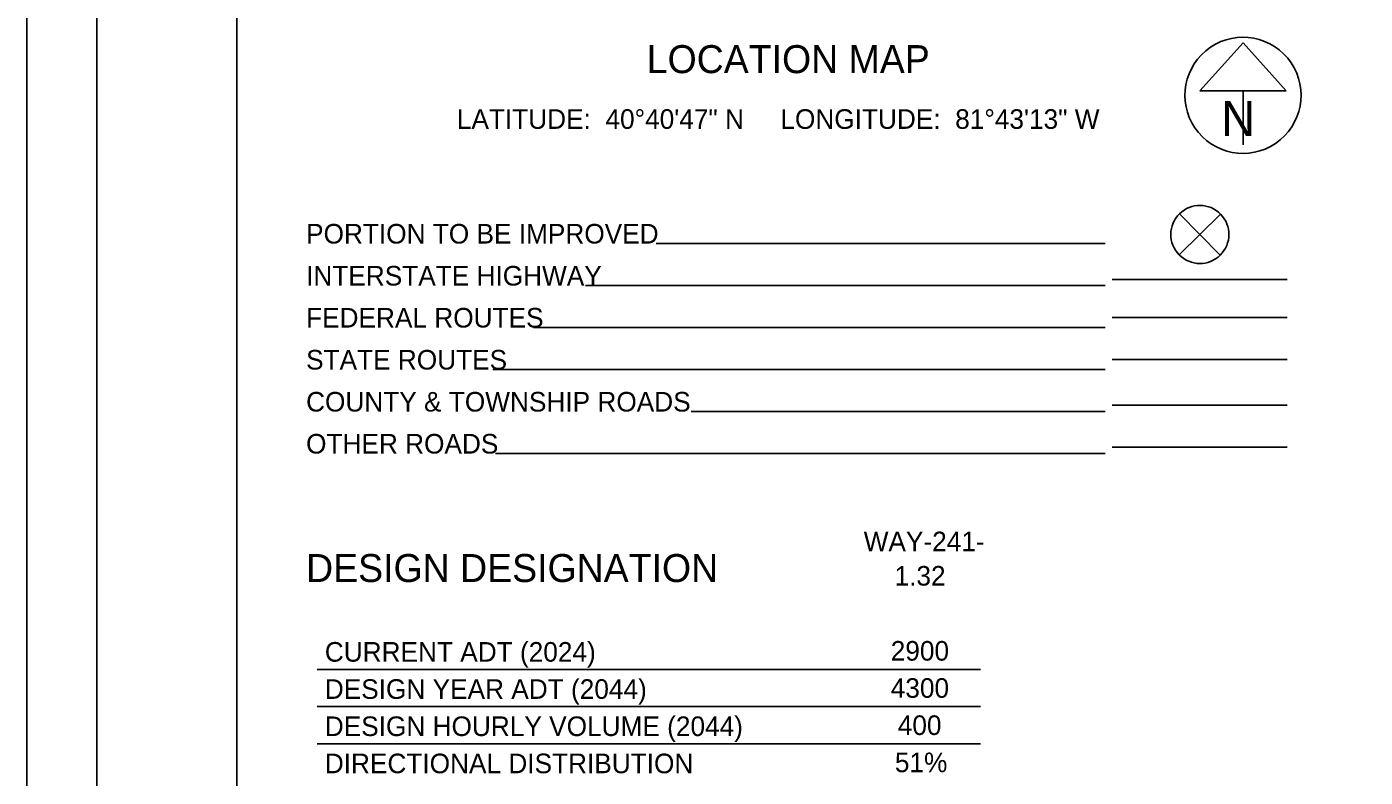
# Model space of a CAD drawing. Extents: x -21.1 to 50.3, y -4.9 to 22.1.
# Drawn here: x 0 to 9.56, y 8.56 to 13.93 of the extents above; entities that cross this region are included whole.
import ezdxf

# ---------------------------------------------------------------- set-up
doc = ezdxf.new("R2010")
doc.units = 0
for name, color, linetype in [('Default', 7, 'Continuous'), ('SH_Border', 7, 'Continuous'), ('SH_Cut_Line', 7, 'Continuous'), ('SH_Data', 7, 'Continuous'), ('SH_Text', 7, 'Continuous')]:
    doc.layers.add(name, color=color, linetype=linetype)

msp = doc.modelspace()

# ---------------------------------------------------------------- linework, layer by layer
at = {"layer": 'Default'}
for p, q in [((2.0726, 9.3348), (6.8094, 9.3348)), ((2.0726, 9.0692), (6.8094, 9.0692)), ((2.0726, 8.8036), (6.8094, 8.8036))]:
    msp.add_line(p, q, dxfattribs=at)
at = {"layer": 'SH_Border'}
for points in [[(0.5, 21.5), (1.5, 21.5), (1.5, 0.5), (0.5, 0.5)], [(1.5, 21.5), (33.5, 21.5), (33.5, 0.5), (1.5, 0.5)]]:
    msp.add_lwpolyline(points, close=True, dxfattribs=at)
at = {"layer": 'SH_Cut_Line'}
msp.add_lwpolyline([(0, 0), (34, 0), (34, 22), (0, 22)], close=True, dxfattribs=at)
at = {"layer": 'SH_Data'}
for p, q in [((8.6845, 13.8091), (8.3769, 13.4678)), ((8.9921, 13.4678), (8.6845, 13.8091)), ((8.3769, 13.4678), (8.9921, 13.4678)), ((8.6845, 13.4678), (8.6845, 13.0811)), ((8.6845, 13.4353), (8.6845, 13.4353)), ((8.6845, 13.4353), (8.6845, 13.4353)), ((8.5245, 12.5868), (8.2285, 12.2962)), ((8.2312, 12.5895), (8.5218, 12.2935)), ((7.7, 12.3767), (4.4937, 12.3767)), ((7.7, 12.0767), (3.9895, 12.0767)), ((9, 12.1207), (7.75, 12.1207)), ((7.7, 11.7767), (3.6192, 11.7767)), ((9, 11.8491), (7.75, 11.8491)), ((7.7, 11.4767), (3.3288, 11.4767)), ((9, 11.5491), (7.75, 11.5491)), ((9, 11.2223), (7.75, 11.2223)), ((7.7, 11.1767), (4.7452, 11.1767)), ((9, 10.9223), (7.75, 10.9223)), ((7.7, 10.8767), (3.3471, 10.8767))]:
    msp.add_line(p, q, dxfattribs=at)
for centre, radius, start, end in [((8.6845, 13.4353), 0.4148, 129.77984, 129.76332), ((8.3765, 12.4415), 0.2074, 134.48425, 134.46773)]:
    msp.add_arc(centre, radius, start, end, dxfattribs=at)

# ---------------------------------------------------------------- texts
at = {"layer": 'Default'}
for s, p in [('WAY-241-', (5.976, 10.1786)), ('1.32', (6.1963, 9.9336)), ('CURRENT ADT (2024)', (2.128, 9.3901)), ('2900', (6.169, 9.3976)), ('DESIGN YEAR ADT (2044)', (2.128, 9.1245)), ('4300', (6.169, 9.132)), ('DESIGN HOURLY VOLUME (2044)', (2.128, 8.8589)), ('400', (6.2193, 8.8664)), ('DIRECTIONAL DISTRIBUTION', (2.128, 8.5933)), ('51%', (6.1987, 8.6008))]:
    msp.add_text(s, height=0.14, dxfattribs=at).set_placement(p)
at = {"layer": 'SH_Data'}
for s, height, p in [('N', 0.25, (8.5292, 13.144)), ('DESIGN DESIGNATION', 0.2, (1.9944, 9.9589))]:
    msp.add_text(s, height=height, dxfattribs=at).set_placement(p)
at = {"layer": 'SH_Text'}
for s, height, p in [('LOCATION MAP', 0.2, (4.4269, 13.5938)), ('LATITUDE:  40°40\'47" N     LONGITUDE:  81°43\'13" W', 0.14, (3.071, 13.1959)), ('PORTION TO BE IMPROVED', 0.14, (1.9944, 12.3767)), ('INTERSTATE HIGHWAY', 0.14, (1.9944, 12.0767)), ('FEDERAL ROUTES', 0.14, (1.9944, 11.7767)), ('STATE ROUTES', 0.14, (1.9944, 11.4767)), ('COUNTY & TOWNSHIP ROADS', 0.14, (1.9944, 11.1767)), ('OTHER ROADS', 0.14, (1.9944, 10.8767))]:
    msp.add_text(s, height=height, dxfattribs=at).set_placement(p)

doc.saveas('drawing.dxf')
